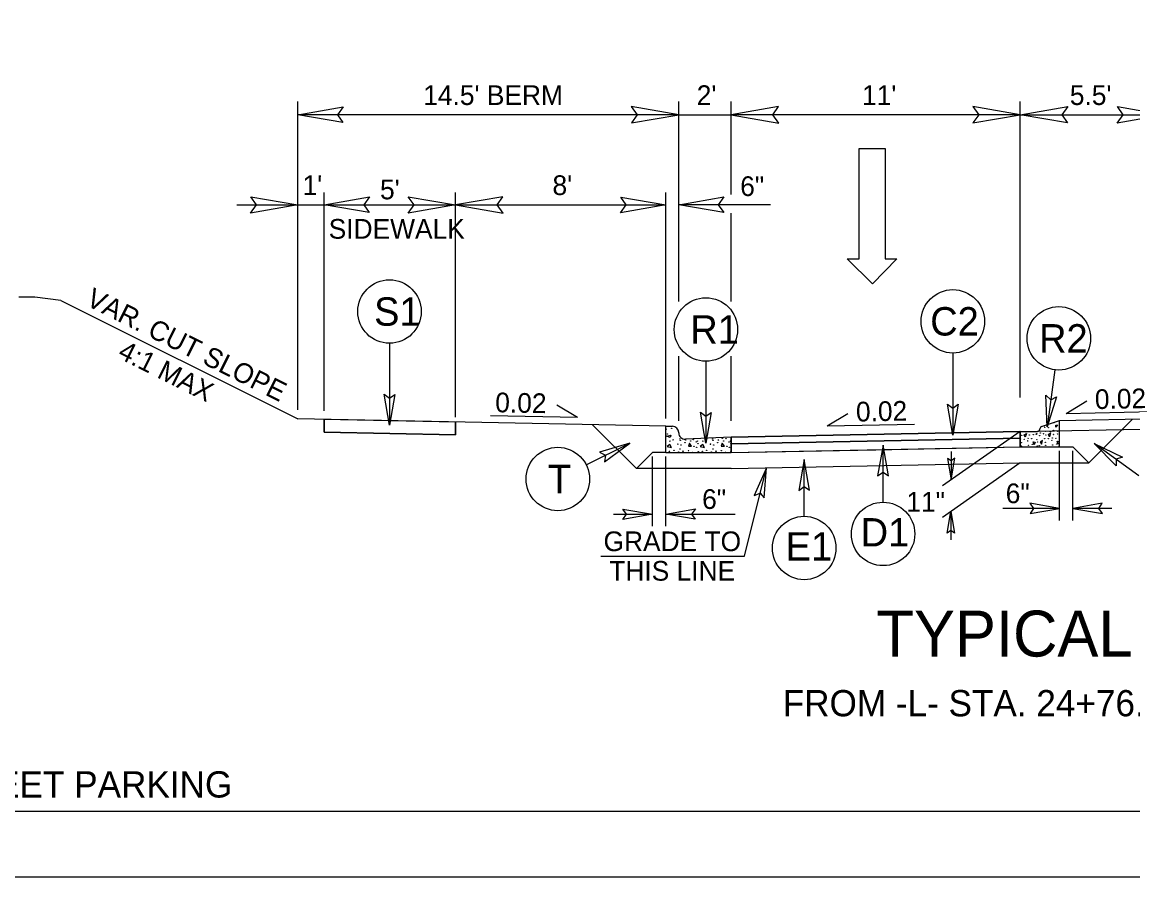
# Model space of a CAD drawing. Extents: x 1487909 to 1489267, y 497866 to 499814.
# Drawn here: x 1488931.46 to 1488973.75, y 498227.52 to 498260.07 of the extents above; entities that cross this region are included whole.
import ezdxf

# ---------------------------------------------------------------- set-up
doc = ezdxf.new("R2010")
doc.units = 0
for name, color, linetype in [('Old_Level_10', 7, 'Continuous'), ('Prop Conc 4in Sidewalk', 7, 'Continuous'), ('Prop Dimension', 7, 'Continuous'), ('Prop Dimension Text', 7, 'Continuous'), ('Prop Lane Arrow CELL', 7, 'Continuous'), ('Prop Shade Light', 7, 'Continuous'), ('Prop Terminator CELL', 7, 'Continuous'), ('Sheet Plot Border Outside CELL', 7, 'Continuous'), ('Sheet Typical CELL', 7, 'Continuous'), ('Typical Curb CELL', 7, 'Continuous'), ('Typical Detail Wedge2 CELL', 7, 'Continuous'), ('Typical Hinge Slope Arterial CELL', 7, 'Continuous'), ('Typical ID Circle CELL', 7, 'Continuous'), ('Typical Pavement Slope CELL', 7, 'Continuous'), ('Typical Pavement Slope Information CELL', 7, 'Continuous'), ('Typical Terminator CELL', 7, 'Continuous'), ('Typical Text ID Circle CELL', 7, 'Continuous')]:
    doc.layers.add(name, color=color, linetype=linetype)

msp = doc.modelspace()

# ---------------------------------------------------------------- linework, layer by layer
at = {"layer": 'Old_Level_10'}
for p, q in [((1488969.464, 498244.233), (1488958.464, 498244.013)), ((1488958.464, 498244.013), (1488958.464, 498243.679)), ((1488963.963, 498243.789), (1488969.464, 498243.899)), ((1488969.464, 498243.899), (1488969.464, 498244.233)), ((1488958.464, 498243.679), (1488963.963, 498243.789))]:
    msp.add_line(p, q, dxfattribs=at)
at = {"layer": 'Prop Conc 4in Sidewalk'}
for p, q in [((1488947.964, 498244.839), (1488942.964, 498244.939)), ((1488942.964, 498244.458), (1488942.964, 498244.939)), ((1488947.964, 498244.839), (1488947.964, 498244.358)), ((1488947.964, 498244.358), (1488942.964, 498244.458))]:
    msp.add_line(p, q, dxfattribs=at)
at = {"layer": 'Prop Dimension'}
for p, q in [((1488941.964, 498245.302), (1488941.964, 498257.045)), ((1488956.464, 498249.434), (1488956.464, 498257.045)), ((1488958.464, 498253.503), (1488958.464, 498257.045)), ((1488969.464, 498245.779), (1488969.464, 498257.045)), ((1488956.464, 498256.545), (1488941.964, 498256.545)), ((1488956.464, 498256.545), (1488958.464, 498256.545)), ((1488969.464, 498256.545), (1488958.464, 498256.545)), ((1488969.464, 498256.545), (1488974.964, 498256.545)), ((1488942.964, 498245.271), (1488942.964, 498253.586)), ((1488947.964, 498245.023), (1488947.964, 498253.586)), ((1488955.964, 498244.98), (1488955.964, 498253.586)), ((1488939.633, 498253.115), (1488941.964, 498253.115)), ((1488941.964, 498253.115), (1488942.964, 498253.115)), ((1488942.964, 498253.115), (1488947.964, 498253.115)), ((1488947.964, 498253.115), (1488955.964, 498253.115)), ((1488959.959, 498253.115), (1488956.464, 498253.115)), ((1488958.464, 498249.434), (1488958.464, 498252.793)), ((1488956.464, 498244.883), (1488956.464, 498247.353)), ((1488958.464, 498244.883), (1488958.464, 498247.353)), ((1488955.464, 498240.873), (1488955.464, 498243.527)), ((1488955.964, 498240.873), (1488955.964, 498243.527)), ((1488970.963, 498241.093), (1488970.963, 498243.747)), ((1488971.463, 498241.093), (1488971.463, 498243.747)), ((1488958.964, 498239.729), (1488959.797, 498243.093)), ((1488970.963, 498241.553), (1488968.802, 498241.553)), ((1488972.95, 498241.553), (1488971.463, 498241.553)), ((1488953.977, 498241.333), (1488955.464, 498241.333)), ((1488955.964, 498241.333), (1488958.612, 498241.333)), ((1488953.491, 498239.729), (1488958.964, 498239.729))]:
    msp.add_line(p, q, dxfattribs=at)
at = {"layer": 'Prop Lane Arrow CELL'}
for p, q in [((1488963.327, 498251.057), (1488963.327, 498255.257)), ((1488963.327, 498255.257), (1488964.317, 498255.257)), ((1488964.317, 498255.257), (1488964.317, 498251.057)), ((1488963.837, 498250.112), (1488962.877, 498251.057)), ((1488962.877, 498251.057), (1488963.327, 498251.057)), ((1488964.767, 498251.057), (1488963.837, 498250.112)), ((1488964.317, 498251.057), (1488964.767, 498251.057))]:
    msp.add_line(p, q, dxfattribs=at)
at = {"layer": 'Prop Shade Light'}
for p, q in [((1488947.964, 498244.839), (1488942.964, 498244.939)), ((1488942.964, 498244.939), (1488942.964, 498244.458)), ((1488947.964, 498244.358), (1488947.964, 498244.839)), ((1488942.964, 498244.458), (1488947.964, 498244.358)), ((1488969.464, 498244.483), (1488958.464, 498244.263)), ((1488969.464, 498244.233), (1488969.464, 498244.483)), ((1488958.464, 498244.263), (1488958.464, 498244.013)), ((1488958.464, 498244.013), (1488969.464, 498244.233))]:
    msp.add_line(p, q, dxfattribs=at)
at = {"layer": 'Prop Terminator CELL'}
for points in [[(1488943.674, 498256.25), (1488941.964, 498256.545), (1488943.683, 498256.849), (1488943.465, 498256.545)], [(1488954.664, 498256.235), (1488956.464, 498256.545), (1488954.654, 498256.865), (1488954.884, 498256.545)], [(1488960.264, 498256.855), (1488958.464, 498256.545), (1488960.274, 498256.225), (1488960.044, 498256.545)], [(1488967.664, 498256.235), (1488969.464, 498256.545), (1488967.654, 498256.865), (1488967.884, 498256.545)], [(1488971.264, 498256.235), (1488969.464, 498256.545), (1488971.274, 498256.865), (1488971.044, 498256.545)], [(1488973.164, 498256.855), (1488974.964, 498256.545), (1488973.154, 498256.225), (1488973.384, 498256.545)], [(1488940.164, 498253.425), (1488941.964, 498253.115), (1488940.154, 498252.795), (1488940.384, 498253.115)], [(1488944.674, 498252.82), (1488942.964, 498253.115), (1488944.683, 498253.419), (1488944.465, 498253.115)], [(1488946.164, 498253.425), (1488947.964, 498253.115), (1488946.154, 498252.795), (1488946.384, 498253.115)], [(1488949.764, 498253.425), (1488947.964, 498253.115), (1488949.774, 498252.795), (1488949.544, 498253.115)], [(1488954.254, 498253.409), (1488955.964, 498253.115), (1488954.244, 498252.811), (1488954.463, 498253.115)], [(1488958.174, 498252.82), (1488956.464, 498253.115), (1488958.183, 498253.419), (1488957.965, 498253.115)], [(1488959.715, 498241.954), (1488959.797, 498243.093), (1488959.331, 498242.043), (1488959.56, 498242.134)], [(1488954.339, 498241.526), (1488955.464, 498241.333), (1488954.333, 498241.133), (1488954.476, 498241.333)], [(1488957.089, 498241.139), (1488955.964, 498241.333), (1488957.095, 498241.533), (1488956.951, 498241.333)], [(1488969.838, 498241.359), (1488970.963, 498241.553), (1488969.832, 498241.753), (1488969.976, 498241.553)], [(1488972.588, 498241.746), (1488971.463, 498241.553), (1488972.595, 498241.353), (1488972.451, 498241.553)]]:
    msp.add_lwpolyline(points, close=True, dxfattribs=at)
at = {"layer": 'Sheet Plot Border Outside CELL'}
msp.add_lwpolyline([(1489051.664, 498337.52), (1488883.264, 498337.52), (1488883.264, 498227.52), (1489051.664, 498227.52)], close=True, dxfattribs=at)
at = {"layer": 'Sheet Typical CELL'}
msp.add_lwpolyline([(1489049.964, 498335.02), (1488899.964, 498335.02), (1488899.964, 498230.02), (1489049.964, 498230.02)], close=True, dxfattribs=at)
at = {"layer": 'Typical Curb CELL'}
for p, q in [((1488970.278, 498244.671), (1488970.963, 498244.899)), ((1488970.963, 498243.899), (1488970.963, 498244.899)), ((1488955.964, 498243.679), (1488955.964, 498244.679)), ((1488955.964, 498244.679), (1488956.224, 498244.679)), ((1488956, 498244.301), (1488956.155, 498244.346)), ((1488956.155, 498244.346), (1488956.138, 498244.255)), ((1488956.464, 498244.429), (1488956.464, 498244.44)), ((1488969.464, 498244.483), (1488969.464, 498243.899)), ((1488969.464, 498244.483), (1488970.12, 498244.483)), ((1488969.464, 498243.899), (1488969.464, 498244.476)), ((1488969.617, 498244.351), (1488969.699, 498244.409)), ((1488969.658, 498244.261), (1488969.617, 498244.351)), ((1488969.699, 498244.409), (1488969.658, 498244.261)), ((1488970.213, 498244.576), (1488970.213, 498244.582)), ((1488970.536, 498244.366), (1488970.618, 498244.425)), ((1488970.577, 498244.275), (1488970.536, 498244.366)), ((1488970.618, 498244.425), (1488970.577, 498244.275)), ((1488970.816, 498244.728), (1488970.902, 498244.728)), ((1488970.821, 498244.641), (1488970.816, 498244.728)), ((1488970.902, 498244.728), (1488970.821, 498244.641)), ((1488956.138, 498244.255), (1488956, 498244.301)), ((1488956.126, 498243.982), (1488956.023, 498243.907)), ((1488956.023, 498243.907), (1488956.189, 498243.868)), ((1488956.189, 498243.868), (1488956.126, 498243.982)), ((1488958.464, 498244.263), (1488956.713, 498244.19)), ((1488956.868, 498244.039), (1488956.834, 498243.925)), ((1488956.834, 498243.925), (1488956.953, 498243.919)), ((1488956.953, 498243.919), (1488956.868, 498244.039)), ((1488957.375, 498243.982), (1488957.272, 498243.907)), ((1488957.272, 498243.907), (1488957.438, 498243.868)), ((1488957.438, 498243.868), (1488957.375, 498243.982)), ((1488958.117, 498244.039), (1488958.082, 498243.925)), ((1488958.082, 498243.925), (1488958.203, 498243.919)), ((1488958.203, 498243.919), (1488958.117, 498244.039)), ((1488958.464, 498243.679), (1488958.464, 498244.263)), ((1488969.464, 498243.899), (1488970.963, 498243.899)), ((1488969.956, 498244.093), (1488970.029, 498244.079)), ((1488969.992, 498243.971), (1488969.956, 498244.093)), ((1488970.029, 498244.079), (1488969.992, 498243.971)), ((1488970.311, 498244.136), (1488970.221, 498244.086)), ((1488970.221, 498244.086), (1488970.279, 498244.005)), ((1488970.279, 498244.005), (1488970.311, 498244.136)), ((1488970.876, 498244.109), (1488970.948, 498244.095)), ((1488970.911, 498243.986), (1488970.876, 498244.109)), ((1488970.948, 498244.095), (1488970.911, 498243.986)), ((1488955.964, 498243.679), (1488958.464, 498243.679))]:
    msp.add_line(p, q, dxfattribs=at)
for centre, radius in [((1488970.753, 498244.813), 0.00635), ((1488955.977, 498244.569), 0.00802), ((1488956.029, 498244.387), 0.00802), ((1488956.194, 498244.603), 0.00802), ((1488969.522, 498244.332), 0.00635), ((1488969.69, 498244.463), 0.00635), ((1488969.811, 498244.351), 0.00635), ((1488969.961, 498244.364), 0.00635), ((1488970.078, 498244.369), 0.00635), ((1488970.094, 498244.398), 0.00635), ((1488970.207, 498244.321), 0.00635), ((1488970.229, 498244.42), 0.00635), ((1488970.351, 498244.393), 0.00635), ((1488970.401, 498244.646), 0.00635), ((1488970.419, 498244.484), 0.00635), ((1488970.441, 498244.348), 0.00635), ((1488970.536, 498244.624), 0.00635), ((1488970.609, 498244.479), 0.00635), ((1488970.726, 498244.529), 0.00635), ((1488970.731, 498244.366), 0.00635), ((1488970.88, 498244.38), 0.00635), ((1488970.889, 498244.488), 0.00635), ((1488956.126, 498244.113), 0.00802), ((1488956.246, 498244.164), 0.00802), ((1488956.423, 498243.999), 0.00802), ((1488956.503, 498244.192), 0.00802), ((1488956.52, 498244.142), 0.00802), ((1488956.548, 498243.971), 0.00802), ((1488956.697, 498244.056), 0.00802), ((1488956.725, 498244.158), 0.00802), ((1488956.919, 498244.119), 0.00802), ((1488957.016, 498244.173), 0.00802), ((1488957.045, 498243.919), 0.00802), ((1488957.125, 498244.079), 0.00802), ((1488957.181, 498244.113), 0.00802), ((1488957.198, 498244.016), 0.00802), ((1488957.375, 498244.113), 0.00802), ((1488957.495, 498244.164), 0.00802), ((1488957.672, 498243.999), 0.00802), ((1488957.752, 498244.192), 0.00802), ((1488957.769, 498244.142), 0.00802), ((1488957.797, 498243.971), 0.00802), ((1488957.946, 498244.056), 0.00802), ((1488957.974, 498244.158), 0.00802), ((1488958.123, 498244.221), 0.00802), ((1488958.168, 498244.119), 0.00802), ((1488958.265, 498244.204), 0.00802), ((1488958.294, 498243.919), 0.00802), ((1488958.374, 498244.079), 0.00802), ((1488958.43, 498244.113), 0.00802), ((1488958.447, 498244.016), 0.00802), ((1488969.473, 498244.192), 0.00635), ((1488969.504, 498244.057), 0.00635), ((1488969.518, 498243.935), 0.00635), ((1488969.617, 498244.188), 0.00635), ((1488969.753, 498244.125), 0.00635), ((1488969.766, 498244.22), 0.00635), ((1488969.78, 498243.953), 0.00635), ((1488969.902, 498244.206), 0.00635), ((1488969.924, 498243.994), 0.00635), ((1488970.1, 498244.165), 0.00635), ((1488970.116, 498244.086), 0.00635), ((1488970.116, 498243.933), 0.00635), ((1488970.193, 498243.946), 0.00635), ((1488970.392, 498244.208), 0.00635), ((1488970.423, 498244.073), 0.00635), ((1488970.437, 498243.951), 0.00635), ((1488970.536, 498244.204), 0.00635), ((1488970.672, 498244.14), 0.00635), ((1488970.685, 498244.235), 0.00635), ((1488970.699, 498243.969), 0.00635), ((1488970.821, 498244.222), 0.00635), ((1488970.844, 498244.009), 0.00635), ((1488956.109, 498243.725), 0.00802), ((1488956.28, 498243.765), 0.00802), ((1488956.457, 498243.702), 0.00802), ((1488956.514, 498243.817), 0.00802), ((1488956.628, 498243.731), 0.00802), ((1488956.834, 498243.754), 0.00802), ((1488956.993, 498243.685), 0.00802), ((1488957.141, 498243.874), 0.00802), ((1488957.204, 498243.708), 0.00802), ((1488957.358, 498243.725), 0.00802), ((1488957.529, 498243.765), 0.00802), ((1488957.706, 498243.702), 0.00802), ((1488957.763, 498243.817), 0.00802), ((1488957.877, 498243.731), 0.00802), ((1488958.083, 498243.754), 0.00802), ((1488958.243, 498243.685), 0.00802), ((1488958.39, 498243.874), 0.00802), ((1488958.453, 498243.708), 0.00802)]:
    msp.add_circle(centre, radius, dxfattribs=at)
for centre, radius, start, end in [((1488956.224, 498244.44), 0.24, 0, 90), ((1488956.703, 498244.429), 0.24, 180, 272.3845), ((1488970.12, 498244.576), 0.0937, 270, 0), ((1488970.307, 498244.582), 0.0937, 108.435, 180), ((1488970.929, 498243.905), 0.00635, 25.7584, 152.9614)]:
    msp.add_arc(centre, radius, start, end, dxfattribs=at)
at = {"layer": 'Typical Detail Wedge2 CELL'}
for p, q in [((1488969.464, 498244.483), (1488966.499, 498242.407)), ((1488966.831, 498243.723), (1488966.831, 498242.639)), ((1488969.464, 498243.286), (1488966.5, 498241.211)), ((1488966.82, 498241.435), (1488966.82, 498240.351))]:
    msp.add_line(p, q, dxfattribs=at)
at = {"layer": 'Typical Hinge Slope Arterial CELL'}
msp.add_line((1488932.935, 498249.474), (1488941.964, 498244.959), dxfattribs=at)
msp.add_lwpolyline([(1488932.935, 498249.474), (1488931.949, 498249.596), (1488931.703, 498249.596), (1488931.333, 498249.596)], dxfattribs=at)
at = {"layer": 'Typical ID Circle CELL'}
for p, q in [((1488945.449, 498247.843), (1488945.449, 498244.72)), ((1488966.899, 498247.469), (1488966.899, 498244.346)), ((1488957.496, 498247.16), (1488957.496, 498244.036)), ((1488970.777, 498246.83), (1488970.495, 498244.665)), ((1488952.939, 498243.209), (1488954.596, 498244.033)), ((1488964.243, 498241.787), (1488964.243, 498243.965)), ((1488973.985, 498242.79), (1488972.28, 498244.025)), ((1488961.239, 498241.252), (1488961.239, 498243.418))]:
    msp.add_line(p, q, dxfattribs=at)
for centre in [(1488945.449, 498249.051), (1488966.899, 498248.677), (1488957.496, 498248.368), (1488970.932, 498248.029), (1488951.857, 498242.671), (1488964.243, 498240.579), (1488961.239, 498240.044)]:
    msp.add_circle(centre, 1.208, dxfattribs=at)
at = {"layer": 'Typical Pavement Slope CELL'}
for p, q in [((1488955.964, 498244.679), (1488941.964, 498244.959)), ((1488970.963, 498244.899), (1488974.964, 498244.979)), ((1488973.745, 498244.955), (1488972.077, 498243.286)), ((1488953.182, 498244.735), (1488954.851, 498243.066)), ((1488958.464, 498244.263), (1488969.464, 498244.483)), ((1488969.464, 498244.483), (1488974.964, 498244.593)), ((1488958.464, 498244.013), (1488969.464, 498244.233)), ((1488958.464, 498243.679), (1488969.464, 498243.899)), ((1488970.963, 498243.899), (1488971.464, 498243.899)), ((1488971.464, 498243.899), (1488972.077, 498243.286)), ((1488955.464, 498243.679), (1488954.851, 498243.066)), ((1488955.964, 498243.679), (1488955.464, 498243.679)), ((1488958.464, 498243.066), (1488954.851, 498243.066)), ((1488958.464, 498243.066), (1488969.464, 498243.286)), ((1488969.464, 498243.286), (1488972.077, 498243.286))]:
    msp.add_line(p, q, dxfattribs=at)
at = {"layer": 'Typical Pavement Slope Information CELL'}
for p, q in [((1488971.215, 498245.173), (1488971.998, 498245.646)), ((1488952.604, 498245.015), (1488951.822, 498245.489)), ((1488962.119, 498244.698), (1488962.902, 498245.172)), ((1488971.215, 498245.173), (1488974.531, 498245.239)), ((1488952.604, 498245.015), (1488949.288, 498245.082)), ((1488962.119, 498244.698), (1488965.435, 498244.765))]:
    msp.add_line(p, q, dxfattribs=at)
at = {"layer": 'Typical Terminator CELL'}
for points in [[(1488945.651, 498245.891), (1488945.449, 498244.72), (1488945.241, 498245.898), (1488945.449, 498245.748)], [(1488945.651, 498245.891), (1488945.449, 498244.72), (1488945.241, 498245.898), (1488945.449, 498245.748)], [(1488970.846, 498245.801), (1488970.495, 498244.665), (1488970.44, 498245.86), (1488970.628, 498245.685)], [(1488957.698, 498245.208), (1488957.496, 498244.036), (1488957.288, 498245.215), (1488957.496, 498245.065)], [(1488957.698, 498245.208), (1488957.496, 498244.036), (1488957.288, 498245.215), (1488957.496, 498245.065)], [(1488967.101, 498245.518), (1488966.899, 498244.346), (1488966.69, 498245.524), (1488966.899, 498245.374)], [(1488953.637, 498243.331), (1488954.596, 498244.033), (1488953.449, 498243.695), (1488953.675, 498243.575)], [(1488964.445, 498242.793), (1488964.243, 498243.965), (1488964.035, 498242.787), (1488964.243, 498242.936)], [(1488973.111, 498243.174), (1488972.28, 498244.025), (1488973.357, 498243.503), (1488973.113, 498243.422)], [(1488961.441, 498242.247), (1488961.239, 498243.418), (1488961.031, 498242.24), (1488961.239, 498242.39)], [(1488966.69, 498243.459), (1488966.831, 498242.639), (1488966.977, 498243.464), (1488966.831, 498243.359)], [(1488966.679, 498240.615), (1488966.82, 498241.435), (1488966.966, 498240.611), (1488966.82, 498240.716)]]:
    msp.add_lwpolyline(points, close=True, dxfattribs=at)

# ---------------------------------------------------------------- texts
at = {"layer": 'Prop Dimension Text'}
for s, p in [("14.5' BERM", (1488946.733, 498256.918)), ("2'", (1488957.147, 498256.918)), ("11'", (1488963.441, 498256.918)), ("5.5'", (1488971.353, 498256.918)), ("1'", (1488942.138, 498253.488)), ("5'", (1488945.088, 498253.325)), ("8'", (1488951.655, 498253.488)), ('6"', (1488958.802, 498253.451)), ('SIDEWALK', (1488943.133, 498251.825)), ('6"', (1488957.352, 498241.532)), ('6"', (1488968.912, 498241.751)), ('11"', (1488965.128, 498241.428)), ('GRADE TO', (1488953.598, 498239.924)), ('THIS LINE', (1488953.816, 498238.799))]:
    msp.add_text(s, height=0.75, dxfattribs=at).set_placement(p)
at = {"layer": 'Typical Hinge Slope Arterial CELL'}
for s, p in [('VAR. CUT SLOPE', (1488933.846, 498249.307)), ('4:1 MAX', (1488935.058, 498247.305))]:
    msp.add_text(s, height=0.75, rotation=333.4658, dxfattribs=at).set_placement(p)
for s, p in [('FROM -L- STA. 24+76.61 TO STA. 25+30.00', (1488960.42, 498233.633)), ('NOTE: SEE PLANS FOR LOCATION OF ON-STREET PARKING', (1488900.454, 498230.539))]:
    msp.add_text(s, height=1, dxfattribs=at).set_placement(p)
at = {"layer": 'Typical Pavement Slope CELL'}
msp.add_text('TYPICAL SECTION 3', height=1.75, dxfattribs=at).set_placement((1488963.989, 498235.908))
at = {"layer": 'Typical Pavement Slope Information CELL'}
for rotation, p in [(1.1457, (1488972.313, 498245.334)), (358.8543, (1488949.468, 498245.217)), (1.1457, (1488963.217, 498244.859))]:
    msp.add_text('0.02', height=0.75, rotation=rotation, dxfattribs=at).set_placement(p)
at = {"layer": 'Typical Text ID Circle CELL'}
for s, height, p in [('S1', 1.0817, (1488944.862, 498248.51)), ('C2', 1.0817, (1488966.037, 498248.137)), ('R1', 1.0817, (1488956.902, 498247.827)), ('R2', 1.0817, (1488970.182, 498247.488)), ('T', 1.082, (1488951.482, 498242.13)), ('D1', 1.0817, (1488963.39, 498240.101)), ('E1', 1.0817, (1488960.533, 498239.565))]:
    msp.add_text(s, height=height, dxfattribs=at).set_placement(p)

doc.saveas('drawing.dxf')
